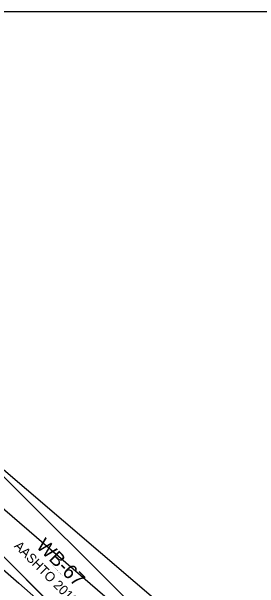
# Model space of a CAD drawing. Extents: x 973688 to 979179, y 703586 to 707602.
# Drawn here: x 973983.9 to 974021.1, y 707477.7 to 707564.2 of the extents above; entities that cross this region are included whole.
import ezdxf

# ---------------------------------------------------------------- set-up
doc = ezdxf.new("R2010")
doc.units = 0
doc.layers.add('0-NPLT', color=7, linetype='Continuous')
doc.layers.add('NO PLOT', color=7, linetype='Continuous')

msp = doc.modelspace()

# ---------------------------------------------------------------- linework, layer by layer
at = {"layer": '0-NPLT'}
msp.add_line((974019.455, 707458.047), (973959.754, 707509.413), dxfattribs=at)
msp.add_line((974019.455, 707458.047), (973959.754, 707509.413), dxfattribs=at)
for points in [[(974005.663, 707459.593), (973969.31, 707495.899), (973954.113, 707508.994), (973959.336, 707515.053), (973974.919, 707501.653), (973975.405, 707501.81), (974008.04, 707473.929)], [(974005.663, 707459.593), (973969.31, 707495.899), (973954.113, 707508.994), (973959.336, 707515.053), (973974.919, 707501.653), (973975.405, 707501.81), (974008.04, 707473.929)], [(973997.278, 707451.833), (973962.769, 707486.578), (973962.742, 707486.634), (973958.846, 707489.954), (973947.473, 707499.735), (973952.689, 707505.8), (973956.756, 707502.409), (973960.825, 707498.989), (973968.456, 707492.503), (973968.8, 707492.568), (973976.941, 707485.581), (973985.037, 707478.534), (973993.08, 707471.434)], [(973997.278, 707451.833), (973962.769, 707486.578), (973962.742, 707486.634), (973958.846, 707489.954), (973947.473, 707499.735), (973952.689, 707505.8), (973956.756, 707502.409), (973960.825, 707498.989), (973968.456, 707492.503), (973968.8, 707492.568), (973976.941, 707485.581), (973985.037, 707478.534), (973993.08, 707471.434)], [(974012.851, 707464.403), (974012.866, 707464.418), (974012.817, 707464.468), (974008.806, 707468.472), (973975.405, 707501.81), (973972.403, 707498.802), (973969.4, 707495.794), (974002.801, 707462.456), (974006.813, 707458.453), (974006.863, 707458.403), (974006.878, 707458.419)], [(974012.851, 707464.403), (974012.866, 707464.418), (974012.817, 707464.468), (974008.806, 707468.472), (973975.405, 707501.81), (973972.403, 707498.802), (973969.4, 707495.794), (974002.801, 707462.456), (974006.813, 707458.453), (974006.863, 707458.403), (974006.878, 707458.419)]]:
    msp.add_lwpolyline(points, dxfattribs=at)
msp.add_arc((973067.39, 706440.089), 1381.396, 47.837979, 50.120132, dxfattribs=at)
msp.add_arc((973067.39, 706440.089), 1381.396, 47.837979, 50.120132, dxfattribs=at)
at = {"layer": 'NO PLOT'}
msp.add_lwpolyline([(973688.494, 707564.199), (974368.494, 707564.199), (974368.494, 707124.199), (973688.494, 707124.199)], close=True, dxfattribs=at)

# ---------------------------------------------------------------- texts
at = {"layer": '0-NPLT'}
for s, height, p in [('WB-67', 2.125, (973987.519, 707483.955)), ('WB-67', 2.125, (973987.519, 707483.955)), ('AASHTO 2018 (US)', 1.41667, (973984.227, 707483.988)), ('AASHTO 2018 (US)', 1.41667, (973984.227, 707483.988)), ('(c) 2021 Transoft Solutions, Inc. All rights reserved.', 0.085, (973989.902, 707481.275)), ('(c) 2021 Transoft Solutions, Inc. All rights reserved.', 0.085, (973989.902, 707481.275))]:
    msp.add_text(s, height=height, rotation=315.05416, dxfattribs=at).set_placement(p)

doc.saveas('drawing.dxf')
